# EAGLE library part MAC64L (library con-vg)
CONNECTOR male, 64 pins, block, type C, rows AC, grid 5.08 mm
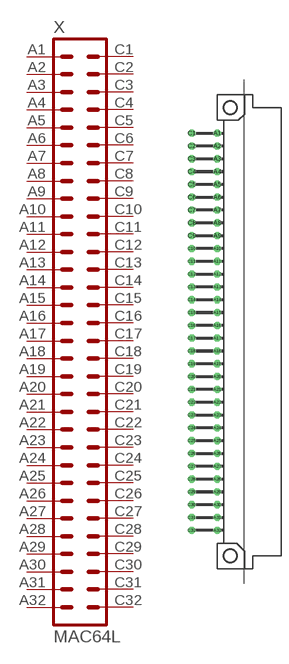
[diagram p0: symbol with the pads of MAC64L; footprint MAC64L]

Designator prefix X

## MAC64L  [MAC64L]
A1  A1  pas
A2  A2  pas
A3  A3  pas
A4  A4  pas
A5  A5  pas
A6  A6  pas
A7  A7  pas
A8  A8  pas
A9  A9  pas
A10  A10  pas
A11  A11  pas
A12  A12  pas
A13  A13  pas
A14  A14  pas
A15  A15  pas
A16  A16  pas
A17  A17  pas
A18  A18  pas
A19  A19  pas
A20  A20  pas
A21  A21  pas
A22  A22  pas
A23  A23  pas
A24  A24  pas
A25  A25  pas
A26  A26  pas
A27  A27  pas
A28  A28  pas
A29  A29  pas
A30  A30  pas
A31  A31  pas
A32  A32  pas
C1  C1  pas
C2  C2  pas
C3  C3  pas
C4  C4  pas
C5  C5  pas
C6  C6  pas
C7  C7  pas
C8  C8  pas
C9  C9  pas
C10  C10  pas
C11  C11  pas
C12  C12  pas
C13  C13  pas
C14  C14  pas
C15  C15  pas
C16  C16  pas
C17  C17  pas
C18  C18  pas
C19  C19  pas
C20  C20  pas
C21  C21  pas
C22  C22  pas
C23  C23  pas
C24  C24  pas
C25  C25  pas
C26  C26  pas
C27  C27  pas
C28  C28  pas
C29  C29  pas
C30  C30  pas
C31  C31  pas
C32  C32  pas

## Footprint MAC64L (pad centres in mm)
CONNECTOR male, 64 pins, type C, rows AC, grid 5.08 mm
drill 0.914 octagon: A1 -2.54,39.37; A2 -2.54,36.83; A3 -2.54,34.29; A4 -2.54,31.75; A5 -2.54,29.21; A6 -2.54,26.67; A7 -2.54,24.13; A8 -2.54,21.59; A9 -2.54,19.05; A10 -2.54,16.51; A11 -2.54,13.97; A12 -2.54,11.43; A13 -2.54,8.89; A14 -2.54,6.35; A15 -2.54,3.81; A16 -2.54,1.27; A17 -2.54,-1.27; A18 -2.54,-3.81; A19 -2.54,-6.35; A20 -2.54,-8.89; A21 -2.54,-11.43; A22 -2.54,-13.97; A23 -2.54,-16.51; A24 -2.54,-19.05; A25 -2.54,-21.59; A26 -2.54,-24.13; A27 -2.54,-26.67; A28 -2.54,-29.21; A29 -2.54,-31.75; A30 -2.54,-34.29; A31 -2.54,-36.83; A32 -2.54,-39.37; C1 -7.62,39.37; C2 -7.62,36.83; C3 -7.62,34.29; C4 -7.62,31.75; C5 -7.62,29.21; C6 -7.62,26.67; C7 -7.62,24.13; C8 -7.62,21.59; C9 -7.62,19.05; C10 -7.62,16.51; C11 -7.62,13.97; C12 -7.62,11.43; C13 -7.62,8.89; C14 -7.62,6.35; C15 -7.62,3.81; C16 -7.62,1.27; C17 -7.62,-1.27; C18 -7.62,-3.81; C19 -7.62,-6.35; C20 -7.62,-8.89; C21 -7.62,-11.43; C22 -7.62,-13.97; C23 -7.62,-16.51; C24 -7.62,-19.05; C25 -7.62,-21.59; C26 -7.62,-24.13; C27 -7.62,-26.67; C28 -7.62,-29.21; C29 -7.62,-31.75; C30 -7.62,-34.29; C31 -7.62,-36.83; C32 -7.62,-39.37
hole 2.794 at 0,44.45
hole 2.794 at 0,-44.45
